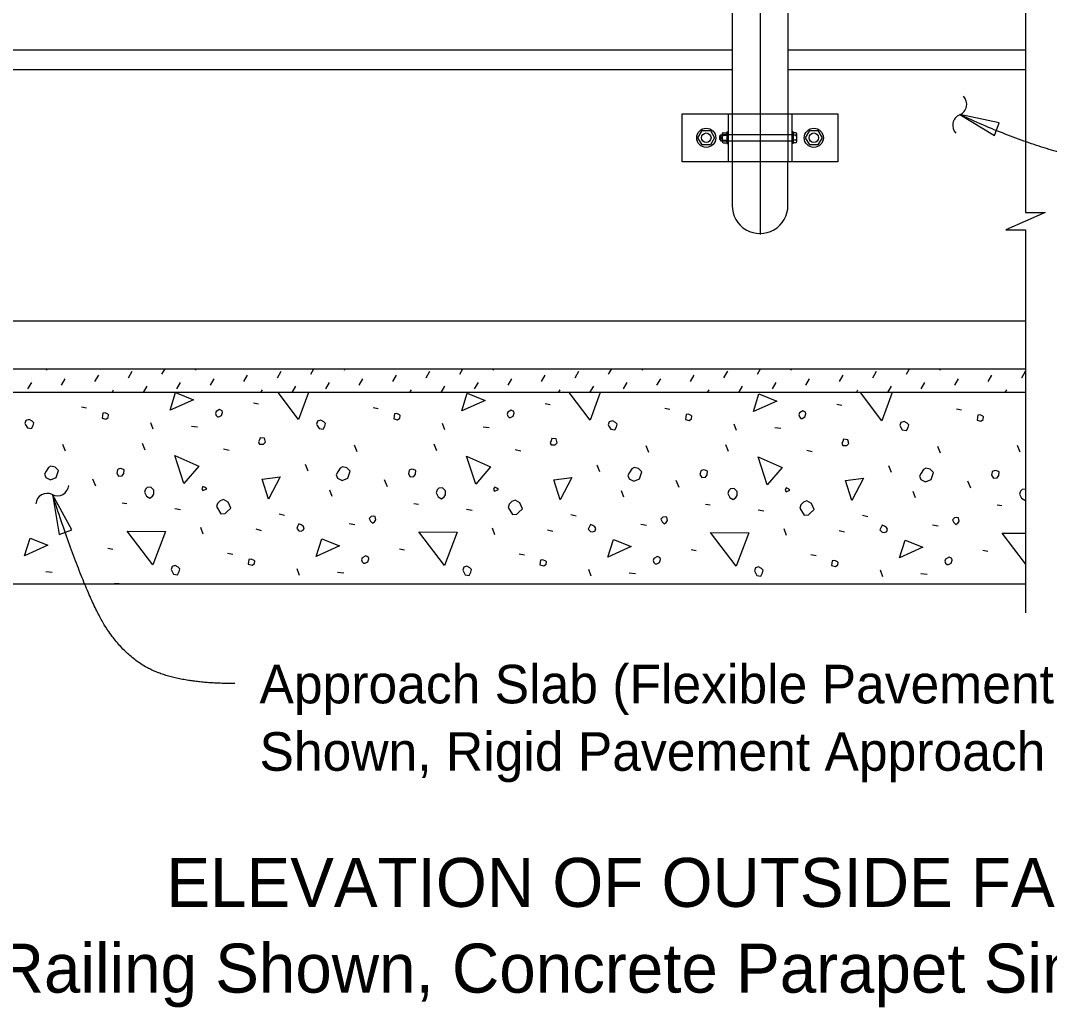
# Model space of a CAD drawing. Extents: x 0 to 41, y -96 to 25.
# Drawn here: x 10.75 to 16.13, y -84.87 to -79.71 of the extents above; entities that cross this region are included whole.
import ezdxf

# ---------------------------------------------------------------- set-up
doc = ezdxf.new("R2010")
doc.units = 0
for name, color, linetype in [('CL_Major', 7, 'Continuous'), ('Dimension', 7, 'Continuous'), ('Miscellaneous', 7, 'Continuous'), ('SteelMisc', 7, 'Continuous'), ('SteelMisc_h', 7, 'Continuous'), ('SupstrConc', 7, 'Continuous'), ('SupstrConc_h', 7, 'Continuous')]:
    doc.layers.add(name, color=color, linetype=linetype)

msp = doc.modelspace()

# ---------------------------------------------------------------- linework, layer by layer
at = {"layer": 'CL_Major'}
msp.add_line((14.615, -71.0824), (14.615, -80.8292), dxfattribs=at)
at = {"layer": 'Dimension'}
msp.add_lwpolyline([(16.002, -78.863), (16.002, -80.7139), (16.1053, -80.7139), (16.002, -80.7589), (15.8987, -80.8039), (16.002, -80.8039), (16.002, -82.8047)], dxfattribs=at)
for points in [[(15.6583, -80.2024), (15.8392, -80.3114), (15.865, -80.2458)], [(10.9179, -82.187), (10.9525, -82.3954), (11.0192, -82.3724)]]:
    msp.add_lwpolyline(points, close=True, dxfattribs=at)
for centre, start, end in [((15.6351, -80.1482), 292.7091, 44.4364), ((15.6811, -80.2581), 112.7091, 224.4364), ((10.8904, -82.2406), 63.2317, 174.9589), ((10.944, -82.1341), 243.2317, 354.9589)]:
    msp.add_arc(centre, 0.0596, start, end, dxfattribs=at)
for points in [[(16.9853, -80.4594), (16.9154, -80.4594), (16.2159, -80.4594), (15.6583, -80.2024)], [(11.8715, -83.1748), (11.6062, -83.1748), (11.3076, -83.0503), (11.092, -82.7183), (10.9179, -82.1871)]]:
    msp.add_open_spline(points, degree=2, dxfattribs=at)
at = {"layer": 'Miscellaneous'}
for p, q in [((14.4075, -80.3301), (14.4075, -80.318)), ((14.4132, -80.3301), (14.4132, -80.318)), ((10.8876, -81.5381), (10.8924, -81.5298)), ((11.4904, -81.5575), (11.5065, -81.5298)), ((11.6655, -81.5381), (11.6703, -81.5298)), ((12.2683, -81.5575), (12.2843, -81.5298)), ((12.4433, -81.5381), (12.4481, -81.5298)), ((13.0461, -81.5575), (13.0621, -81.5298)), ((13.2211, -81.5381), (13.2259, -81.5298)), ((13.8239, -81.5575), (13.84, -81.5298)), ((13.9989, -81.5381), (14.0037, -81.5298)), ((14.6017, -81.5575), (14.6178, -81.5298)), ((14.7767, -81.5381), (14.7815, -81.5298)), ((15.3795, -81.5575), (15.3956, -81.5298)), ((15.5545, -81.5381), (15.5593, -81.5298)), ((10.9654, -81.6158), (10.9849, -81.5823)), ((11.1404, -81.5964), (11.1599, -81.5628)), ((11.3154, -81.577), (11.3349, -81.5434)), ((11.7432, -81.6158), (11.7627, -81.5823)), ((11.9182, -81.5964), (11.9377, -81.5628)), ((12.0933, -81.577), (12.1127, -81.5434)), ((12.5211, -81.6158), (12.5405, -81.5823)), ((12.6961, -81.5964), (12.7155, -81.5628)), ((12.8711, -81.577), (12.8905, -81.5434)), ((13.2989, -81.6158), (13.3183, -81.5823)), ((13.4739, -81.5964), (13.4933, -81.5628)), ((13.6489, -81.577), (13.6683, -81.5434)), ((14.0767, -81.6158), (14.0961, -81.5823)), ((14.2517, -81.5964), (14.2711, -81.5628)), ((14.4267, -81.577), (14.4462, -81.5434)), ((14.8545, -81.6158), (14.874, -81.5823)), ((15.0295, -81.5964), (15.049, -81.5628)), ((15.2045, -81.577), (15.224, -81.5434)), ((15.6323, -81.6158), (15.6518, -81.5823)), ((15.8073, -81.5964), (15.8268, -81.5628)), ((15.9823, -81.577), (16.0018, -81.5434)), ((10.7904, -81.6353), (10.8099, -81.6017)), ((11.2295, -81.6547), (11.2377, -81.6406)), ((11.3932, -81.6547), (11.4127, -81.6211)), ((11.5682, -81.6353), (11.5877, -81.6017)), ((12.0073, -81.6547), (12.0155, -81.6406)), ((12.171, -81.6547), (12.1905, -81.6211)), ((12.346, -81.6353), (12.3655, -81.6017)), ((12.7851, -81.6547), (12.7933, -81.6406)), ((12.9489, -81.6547), (12.9683, -81.6211)), ((13.1239, -81.6353), (13.1433, -81.6017)), ((13.5629, -81.6547), (13.5711, -81.6406)), ((13.7267, -81.6547), (13.7461, -81.6211)), ((13.9017, -81.6353), (13.9211, -81.6017)), ((14.3407, -81.6547), (14.3489, -81.6406)), ((14.5045, -81.6547), (14.5239, -81.6211)), ((14.6795, -81.6353), (14.6989, -81.6017)), ((15.1186, -81.6547), (15.1267, -81.6406)), ((15.2823, -81.6547), (15.3018, -81.6211)), ((15.4573, -81.6353), (15.4768, -81.6017)), ((15.8964, -81.6547), (15.9046, -81.6406)), ((11.0699, -81.729), (11.0964, -81.7343)), ((11.9679, -81.7078), (11.9945, -81.7131)), ((12.5937, -81.7325), (12.6202, -81.7378)), ((13.4917, -81.7113), (13.5183, -81.7166)), ((14.1175, -81.736), (14.1441, -81.7414)), ((15.0156, -81.7148), (15.0421, -81.7201)), ((15.6414, -81.7396), (15.6679, -81.7449)), ((11.4447, -81.8457), (11.4323, -81.8121)), ((11.6444, -81.8297), (11.6763, -81.8333)), ((12.9685, -81.8492), (12.9561, -81.8156)), ((13.1682, -81.8333), (13.2001, -81.8368)), ((14.4923, -81.8527), (14.4799, -81.8191)), ((14.6921, -81.8368), (14.7239, -81.8403)), ((10.9868, -81.9606), (10.9727, -81.9252)), ((11.4022, -81.9553), (11.3881, -81.9199)), ((11.8124, -81.9482), (11.8407, -81.9553)), ((12.5106, -81.9641), (12.4965, -81.9287)), ((12.9261, -81.9588), (12.9119, -81.9234)), ((13.3362, -81.9517), (13.3645, -81.9588)), ((14.0345, -81.9676), (14.0203, -81.9323)), ((14.4499, -81.9623), (14.4357, -81.927)), ((14.86, -81.9553), (14.8883, -81.9623)), ((15.5583, -81.9712), (15.5441, -81.9358)), ((15.9737, -81.9659), (15.9596, -81.9305)), ((12.2543, -82.0649), (12.2402, -82.0295)), ((13.7781, -82.0684), (13.764, -82.033)), ((15.3019, -82.0719), (15.2878, -82.0366)), ((11.1442, -82.1426), (11.13, -82.1073)), ((12.668, -82.1462), (12.6538, -82.1108)), ((14.1918, -82.1497), (14.1776, -82.1144)), ((15.7156, -82.1532), (15.7015, -82.1179)), ((12.3798, -82.1974), (12.3675, -82.1638)), ((13.9036, -82.201), (13.8913, -82.1674)), ((15.4275, -82.2045), (15.4151, -82.1709)), ((11.282, -82.231), (11.3068, -82.2346)), ((12.8059, -82.2346), (12.8306, -82.2381)), ((14.3297, -82.2381), (14.3544, -82.2416)), ((15.8535, -82.2416), (15.8782, -82.2452)), ((11.5578, -82.2593), (11.5879, -82.2646)), ((12.1023, -82.2876), (12.1306, -82.2947)), ((13.0816, -82.2628), (13.1117, -82.2681)), ((13.6261, -82.2911), (13.6544, -82.2982)), ((14.6054, -82.2664), (14.6355, -82.2717)), ((15.1499, -82.2947), (15.1782, -82.3017)), ((12.4682, -82.3389), (12.4983, -82.3442)), ((13.992, -82.3424), (14.0221, -82.3477)), ((15.5158, -82.3459), (15.5459, -82.3512)), ((11.7063, -82.3937), (11.6939, -82.3601)), ((11.9803, -82.3671), (12.0086, -82.3742)), ((13.2301, -82.3972), (13.2177, -82.3636)), ((13.5041, -82.3707), (13.5324, -82.3777)), ((14.7539, -82.4007), (14.7416, -82.3671)), ((15.0279, -82.3742), (15.0562, -82.3813)), ((11.2078, -82.4679), (11.2343, -82.4732)), ((11.8336, -82.4927), (11.8601, -82.498)), ((12.7316, -82.4714), (12.7581, -82.4767)), ((13.3574, -82.4962), (13.3839, -82.5015)), ((14.2554, -82.475), (14.2819, -82.4803)), ((14.8812, -82.4997), (14.9077, -82.505)), ((15.7792, -82.4785), (15.8058, -82.4838)), ((10.8843, -82.5899), (10.9161, -82.5934)), ((12.2084, -82.6093), (12.196, -82.5757)), ((12.4081, -82.5934), (12.4399, -82.597)), ((13.7322, -82.6129), (13.7198, -82.5793)), ((13.9319, -82.597), (13.9637, -82.6005)), ((15.256, -82.6164), (15.2436, -82.5828)), ((15.4557, -82.6005), (15.4876, -82.604))]:
    msp.add_line(p, q, dxfattribs=at)
for points in [[(11.5331, -81.7467), (11.5613, -81.6547), (11.655, -81.6919), (11.5331, -81.7467)], [(12.203, -81.7944), (12.0969, -81.6547)], [(12.2552, -81.6547), (12.203, -81.7944)], [(13.0569, -81.7502), (13.0852, -81.6583), (13.1789, -81.6954), (13.0569, -81.7502)], [(13.7269, -81.7979), (13.618, -81.6547)], [(13.7804, -81.6547), (13.7269, -81.7979)], [(14.5807, -81.7537), (14.609, -81.6618), (14.7027, -81.6989), (14.5807, -81.7537)], [(15.2507, -81.8015), (15.1392, -81.6547)], [(15.3055, -81.6547), (15.2507, -81.8015)], [(11.7806, -81.782), (11.7876, -81.782), (11.8018, -81.7749), (11.8071, -81.759), (11.8053, -81.7502), (11.7912, -81.7431), (11.7735, -81.7537), (11.7699, -81.7643), (11.7735, -81.7749), (11.7806, -81.782)], [(13.3044, -81.7855), (13.3114, -81.7855), (13.3256, -81.7785), (13.3309, -81.7626), (13.3291, -81.7537), (13.315, -81.7467), (13.2973, -81.7573), (13.2938, -81.7679), (13.2973, -81.7785), (13.3044, -81.7855)], [(14.8282, -81.7891), (14.8353, -81.7891), (14.8494, -81.782), (14.8547, -81.7661), (14.8529, -81.7573), (14.8388, -81.7502), (14.8211, -81.7608), (14.8176, -81.7714), (14.8211, -81.782), (14.8282, -81.7891)], [(10.7782, -81.8227), (10.7871, -81.8386), (10.8083, -81.8421), (10.8171, -81.8262), (10.8207, -81.8121), (10.8118, -81.8032), (10.7959, -81.7944), (10.78, -81.7997), (10.7747, -81.8156), (10.7782, -81.8227)], [(11.1777, -81.7873), (11.1972, -81.7926), (11.2096, -81.7838), (11.2113, -81.7714), (11.2078, -81.7679), (11.1937, -81.7608), (11.1813, -81.7626), (11.1795, -81.7749), (11.1777, -81.7873)], [(12.302, -81.8262), (12.3109, -81.8421), (12.3321, -81.8457), (12.3409, -81.8297), (12.3445, -81.8156), (12.3356, -81.8068), (12.3197, -81.7979), (12.3038, -81.8032), (12.2985, -81.8191), (12.302, -81.8262)], [(12.7016, -81.7909), (12.721, -81.7962), (12.7334, -81.7873), (12.7351, -81.7749), (12.7316, -81.7714), (12.7175, -81.7643), (12.7051, -81.7661), (12.7033, -81.7785), (12.7016, -81.7909)], [(13.8259, -81.8297), (13.8347, -81.8457), (13.8559, -81.8492), (13.8647, -81.8333), (13.8683, -81.8191), (13.8594, -81.8103), (13.8435, -81.8015), (13.8276, -81.8068), (13.8223, -81.8227), (13.8259, -81.8297)], [(14.2254, -81.7944), (14.2448, -81.7997), (14.2572, -81.7909), (14.259, -81.7785), (14.2554, -81.7749), (14.2413, -81.7679), (14.2289, -81.7696), (14.2271, -81.782), (14.2254, -81.7944)], [(15.3497, -81.8333), (15.3585, -81.8492), (15.3797, -81.8527), (15.3886, -81.8368), (15.3921, -81.8227), (15.3833, -81.8138), (15.3674, -81.805), (15.3514, -81.8103), (15.3461, -81.8262), (15.3497, -81.8333)], [(15.7492, -81.7979), (15.7686, -81.8032), (15.781, -81.7944), (15.7828, -81.782), (15.7792, -81.7785), (15.7651, -81.7714), (15.7527, -81.7732), (15.751, -81.7855), (15.7492, -81.7979)], [(11.9998, -81.9234), (12.021, -81.9234), (12.0316, -81.9128), (12.0263, -81.8934), (12.0033, -81.8916), (11.9998, -81.9022), (11.9945, -81.9111), (11.9998, -81.9234), (11.9962, -81.9199)], [(13.5236, -81.927), (13.5448, -81.927), (13.5554, -81.9164), (13.5501, -81.8969), (13.5271, -81.8951), (13.5236, -81.9058), (13.5183, -81.9146), (13.5236, -81.927), (13.52, -81.9234)], [(15.0474, -81.9305), (15.0686, -81.9305), (15.0792, -81.9199), (15.0739, -81.9005), (15.0509, -81.8987), (15.0474, -81.9093), (15.0421, -81.9181), (15.0474, -81.9305), (15.0438, -81.927)], [(11.6055, -82.1303), (11.5578, -81.9835), (11.6833, -82.0383), (11.6055, -82.1303)], [(13.1294, -82.1338), (13.0816, -81.9871), (13.2071, -82.0419), (13.1294, -82.1338)], [(14.6532, -82.1373), (14.6054, -81.9906), (14.731, -82.0454), (14.6532, -82.1373)], [(10.8843, -82.0984), (10.9073, -82.1108), (10.9373, -82.0984), (10.9497, -82.0613), (10.932, -82.0436), (10.909, -82.0383), (10.8984, -82.0454), (10.8861, -82.0649), (10.8772, -82.0808), (10.8843, -82.0984)], [(11.2538, -82.0755), (11.2626, -82.0914), (11.282, -82.0896), (11.2909, -82.0772), (11.2926, -82.0578), (11.2803, -82.0525), (11.2714, -82.0507), (11.2608, -82.0542), (11.2573, -82.0578), (11.2538, -82.0755)], [(12.4081, -82.102), (12.4311, -82.1144), (12.4611, -82.102), (12.4735, -82.0649), (12.4558, -82.0472), (12.4329, -82.0419), (12.4223, -82.0489), (12.4099, -82.0684), (12.401, -82.0843), (12.4081, -82.102)], [(12.7776, -82.079), (12.7864, -82.0949), (12.8059, -82.0931), (12.8147, -82.0808), (12.8165, -82.0613), (12.8041, -82.056), (12.7952, -82.0542), (12.7846, -82.0578), (12.7811, -82.0613), (12.7776, -82.079)], [(13.9319, -82.1055), (13.9549, -82.1179), (13.985, -82.1055), (13.9973, -82.0684), (13.9797, -82.0507), (13.9567, -82.0454), (13.9461, -82.0525), (13.9337, -82.0719), (13.9249, -82.0878), (13.9319, -82.1055)], [(14.3014, -82.0825), (14.3102, -82.0984), (14.3297, -82.0967), (14.3385, -82.0843), (14.3403, -82.0649), (14.3279, -82.0596), (14.3191, -82.0578), (14.3085, -82.0613), (14.3049, -82.0649), (14.3014, -82.0825)], [(15.4557, -82.109), (15.4787, -82.1214), (15.5088, -82.109), (15.5211, -82.0719), (15.5035, -82.0542), (15.4805, -82.0489), (15.4699, -82.056), (15.4575, -82.0755), (15.4487, -82.0914), (15.4557, -82.109)], [(15.8252, -82.0861), (15.834, -82.102), (15.8535, -82.1002), (15.8623, -82.0878), (15.8641, -82.0684), (15.8517, -82.0631), (15.8429, -82.0613), (15.8323, -82.0649), (15.8287, -82.0684), (15.8252, -82.0861)], [(12.0475, -82.2116), (12.0139, -82.1073), (12.1076, -82.0949), (12.0475, -82.2116)], [(13.5713, -82.2151), (13.5377, -82.1108), (13.6314, -82.0984), (13.5713, -82.2151)], [(15.0951, -82.2187), (15.0615, -82.1144), (15.1552, -82.102), (15.0951, -82.2187)], [(11.3987, -82.1745), (11.4093, -82.1957), (11.427, -82.2063), (11.4411, -82.1957), (11.4482, -82.1851), (11.4482, -82.1638), (11.4323, -82.1479), (11.4129, -82.1497), (11.404, -82.1585), (11.3987, -82.1745)], [(11.7045, -82.1656), (11.724, -82.1568), (11.7169, -82.1497), (11.7045, -82.1444), (11.6992, -82.1568), (11.7045, -82.1656)], [(12.9225, -82.178), (12.9331, -82.1992), (12.9508, -82.2098), (12.965, -82.1992), (12.972, -82.1886), (12.972, -82.1674), (12.9561, -82.1515), (12.9367, -82.1532), (12.9278, -82.1621), (12.9225, -82.178)], [(13.2284, -82.1692), (13.2478, -82.1603), (13.2407, -82.1532), (13.2284, -82.1479), (13.223, -82.1603), (13.2284, -82.1692)], [(14.4463, -82.1815), (14.457, -82.2027), (14.4746, -82.2133), (14.4888, -82.2027), (14.4958, -82.1921), (14.4958, -82.1709), (14.4799, -82.155), (14.4605, -82.1568), (14.4516, -82.1656), (14.4463, -82.1815)], [(14.7522, -82.1727), (14.7716, -82.1638), (14.7645, -82.1568), (14.7522, -82.1515), (14.7469, -82.1638), (14.7522, -82.1727)], [(16.002, -82.1587), (15.9843, -82.1603), (15.9755, -82.1692), (15.9702, -82.1851)], [(15.9702, -82.1851), (15.9808, -82.2063), (15.9984, -82.2169), (16.002, -82.2142)], [(11.7752, -82.2505), (11.7982, -82.2876), (11.8212, -82.2858), (11.83, -82.277), (11.8495, -82.2575), (11.8371, -82.2275), (11.8124, -82.2133), (11.7947, -82.2204), (11.7806, -82.2346), (11.7752, -82.2505)], [(13.2991, -82.254), (13.322, -82.2911), (13.345, -82.2894), (13.3539, -82.2805), (13.3733, -82.2611), (13.3609, -82.231), (13.3362, -82.2169), (13.3185, -82.224), (13.3044, -82.2381), (13.2991, -82.254)], [(14.8229, -82.2575), (14.8459, -82.2947), (14.8688, -82.2929), (14.8777, -82.2841), (14.8971, -82.2646), (14.8848, -82.2346), (14.86, -82.2204), (14.8423, -82.2275), (14.8282, -82.2416), (14.8229, -82.2575)], [(12.2048, -82.376), (12.2172, -82.3777), (12.2296, -82.3724), (12.2331, -82.3618), (12.2278, -82.353), (12.2172, -82.3459), (12.2048, -82.3406), (12.1977, -82.3548), (12.1942, -82.3654), (12.2048, -82.376)], [(12.5796, -82.3265), (12.5902, -82.3371), (12.6008, -82.33), (12.6079, -82.3194), (12.6043, -82.3017), (12.5955, -82.3), (12.5831, -82.3017), (12.5725, -82.3123), (12.5796, -82.3265)], [(13.7286, -82.3795), (13.741, -82.3813), (13.7534, -82.376), (13.7569, -82.3654), (13.7516, -82.3565), (13.741, -82.3495), (13.7286, -82.3442), (13.7216, -82.3583), (13.718, -82.3689), (13.7286, -82.3795)], [(14.1034, -82.33), (14.114, -82.3406), (14.1246, -82.3336), (14.1317, -82.3229), (14.1281, -82.3053), (14.1193, -82.3035), (14.1069, -82.3053), (14.0963, -82.3159), (14.1034, -82.33)], [(15.2524, -82.3831), (15.2648, -82.3848), (15.2772, -82.3795), (15.2807, -82.3689), (15.2754, -82.3601), (15.2648, -82.353), (15.2524, -82.3477), (15.2454, -82.3618), (15.2418, -82.3724), (15.2524, -82.3831)], [(15.6272, -82.3336), (15.6378, -82.3442), (15.6484, -82.3371), (15.6555, -82.3265), (15.652, -82.3088), (15.6431, -82.307), (15.6307, -82.3088), (15.6201, -82.3194), (15.6272, -82.3336)], [(11.4429, -82.5545), (11.3086, -82.3777), (11.5083, -82.3795), (11.4429, -82.5545)], [(12.9667, -82.5581), (12.8324, -82.3813), (13.0321, -82.3831), (12.9667, -82.5581)], [(14.4905, -82.5616), (14.3562, -82.3848), (14.5559, -82.3866), (14.4905, -82.5616)], [(16.002, -82.5489), (15.88, -82.3884), (16.002, -82.3894)], [(10.7729, -82.5068), (10.8012, -82.4149), (10.8949, -82.452), (10.7729, -82.5068)], [(12.2967, -82.5103), (12.325, -82.4184), (12.4187, -82.4555), (12.2967, -82.5103)], [(13.8206, -82.5139), (13.8488, -82.4219), (13.9425, -82.4591), (13.8206, -82.5139)], [(15.3444, -82.5174), (15.3727, -82.4255), (15.4663, -82.4626), (15.3444, -82.5174)], [(12.5442, -82.5457), (12.5513, -82.5457), (12.5654, -82.5386), (12.5707, -82.5227), (12.569, -82.5139), (12.5548, -82.5068), (12.5372, -82.5174), (12.5336, -82.528), (12.5372, -82.5386), (12.5442, -82.5457)], [(14.068, -82.5492), (14.0751, -82.5492), (14.0893, -82.5422), (14.0946, -82.5262), (14.0928, -82.5174), (14.0786, -82.5103), (14.061, -82.5209), (14.0574, -82.5315), (14.061, -82.5422), (14.068, -82.5492)], [(11.5419, -82.5863), (11.5507, -82.6023), (11.572, -82.6058), (11.5808, -82.5899), (11.5843, -82.5757), (11.5755, -82.5669), (11.5596, -82.5581), (11.5437, -82.5634), (11.5384, -82.5793), (11.5419, -82.5863)], [(11.9414, -82.551), (11.9609, -82.5563), (11.9732, -82.5475), (11.975, -82.5351), (11.9715, -82.5315), (11.9573, -82.5245), (11.945, -82.5262), (11.9432, -82.5386), (11.9414, -82.551)], [(13.0657, -82.5899), (13.0746, -82.6058), (13.0958, -82.6093), (13.1046, -82.5934), (13.1081, -82.5793), (13.0993, -82.5704), (13.0834, -82.5616), (13.0675, -82.5669), (13.0622, -82.5828), (13.0657, -82.5899)], [(13.4652, -82.5545), (13.4847, -82.5598), (13.4971, -82.551), (13.4988, -82.5386), (13.4953, -82.5351), (13.4811, -82.528), (13.4688, -82.5298), (13.467, -82.5422), (13.4652, -82.5545)], [(14.989, -82.5581), (15.0085, -82.5634), (15.0209, -82.5545), (15.0226, -82.5422), (15.0191, -82.5386), (15.005, -82.5315), (14.9926, -82.5333), (14.9908, -82.5457), (14.989, -82.5581)], [(15.5919, -82.5528), (15.5989, -82.5528), (15.6131, -82.5457), (15.6184, -82.5298), (15.6166, -82.5209), (15.6025, -82.5139), (15.5848, -82.5245), (15.5813, -82.5351), (15.5848, -82.5457), (15.5919, -82.5528)], [(14.5895, -82.5934), (14.5984, -82.6093), (14.6196, -82.6129), (14.6284, -82.597), (14.632, -82.5828), (14.6231, -82.574), (14.6072, -82.5651), (14.5913, -82.5704), (14.586, -82.5863), (14.5895, -82.5934)], [(11.2665, -82.6547), (11.2661, -82.6535), (11.2432, -82.6518), (11.2422, -82.6547)]]:
    msp.add_lwpolyline(points, dxfattribs=at)
at = {"layer": 'SteelMisc'}
for p, q in [((14.4692, -79.4482), (14.4692, -80.1982)), ((14.7609, -79.4482), (14.7609, -80.1982)), ((14.2091, -80.1982), (15.021, -80.1982)), ((14.2091, -80.4482), (14.2091, -80.1982)), ((14.4484, -80.1982), (14.4484, -80.4482)), ((14.7817, -80.1982), (14.7817, -80.4482)), ((15.021, -80.1982), (15.021, -80.4482)), ((14.4168, -80.3053), (14.4168, -80.341)), ((14.4217, -80.2972), (14.4418, -80.2972)), ((14.4418, -80.2929), (14.4418, -80.3535)), ((14.4418, -80.2929), (14.4484, -80.2929)), ((14.4418, -80.2972), (14.4418, -80.3492)), ((14.788, -80.2929), (14.782, -80.2929)), ((14.788, -80.2929), (14.788, -80.3535)), ((14.8027, -80.2972), (14.788, -80.2972)), ((14.8078, -80.3426), (14.8078, -80.3037)), ((14.4047, -80.3152), (14.4103, -80.3086)), ((14.4047, -80.3329), (14.4047, -80.3152)), ((14.4047, -80.3329), (14.4103, -80.3385)), ((14.4103, -80.3086), (14.4168, -80.3086)), ((14.4103, -80.3385), (14.4103, -80.3086)), ((14.4103, -80.3385), (14.4168, -80.3385)), ((14.4215, -80.3102), (14.4418, -80.3102)), ((14.4215, -80.3361), (14.4418, -80.3361)), ((14.4218, -80.3492), (14.4418, -80.3492)), ((14.4418, -80.3535), (14.4484, -80.3535)), ((14.788, -80.3535), (14.782, -80.3535)), ((14.8028, -80.3102), (14.788, -80.3102)), ((14.8028, -80.3362), (14.788, -80.3362)), ((14.8027, -80.3492), (14.788, -80.3492)), ((15.021, -80.4482), (14.2091, -80.4482)), ((14.4691, -80.4482), (14.4691, -80.6774)), ((14.7608, -80.6774), (14.7608, -80.4482))]:
    msp.add_line(p, q, dxfattribs=at)
for points in [[(14.3124, -80.2857), (14.3557, -80.2857), (14.3774, -80.3232), (14.3557, -80.3607), (14.3124, -80.3607), (14.2907, -80.3232)], [(14.8744, -80.2857), (14.9177, -80.2857), (14.9394, -80.3232), (14.9177, -80.3607), (14.8744, -80.3607), (14.8527, -80.3232)]]:
    msp.add_lwpolyline(points, close=True, dxfattribs=at)
for centre, radius in [((14.3341, -80.3232), 0.05), ((14.3341, -80.3232), 0.025), ((14.896, -80.3232), 0.05), ((14.896, -80.3232), 0.025)]:
    msp.add_circle(centre, radius, dxfattribs=at)
for centre, radius, start, end in [((14.4234, -80.3038), 0.00674, 104.4891, 254.1889), ((14.801, -80.3038), 0.00673, 285.7823, 75.5404), ((14.4363, -80.3232), 0.0196, 138.628, 221.372), ((14.4234, -80.3427), 0.00673, 105.7823, 255.5404), ((14.801, -80.3427), 0.00674, 284.4891, 74.1889), ((14.7881, -80.3232), 0.0196, 318.628, 41.372)]:
    msp.add_arc(centre, radius, start, end, dxfattribs=at)
msp.add_ellipse((14.615, -80.6774), major_axis=(0, 0.1458), ratio=0.999499, start_param=1.570796, end_param=4.712389, dxfattribs=at)
at = {"layer": 'SteelMisc_h'}
for p, q in [((14.4692, -80.1982), (14.4692, -80.4482)), ((14.7609, -80.1982), (14.7609, -80.4482)), ((14.7817, -80.3086), (14.4168, -80.3086)), ((14.4168, -80.3385), (14.7817, -80.3385))]:
    msp.add_line(p, q, dxfattribs=at)
at = {"layer": 'SupstrConc'}
for p, q in [((4.7609, -79.8631), (14.4692, -79.8631)), ((14.7609, -79.8631), (16.002, -79.8631)), ((4.7609, -79.9673), (14.4692, -79.9673)), ((14.7609, -79.9673), (16.002, -79.9673)), ((3.615, -81.5298), (16.002, -81.5298)), ((16.002, -81.6547), (3.615, -81.6547)), ((16.002, -82.6547), (3.615, -82.6547))]:
    msp.add_line(p, q, dxfattribs=at)
at = {"layer": 'SupstrConc_h'}
msp.add_line((3.615, -81.2797), (16.002, -81.2797), dxfattribs=at)

# ---------------------------------------------------------------- texts
at = {"layer": 'Dimension'}
for s, height, p in [('Approach Slab (Flexible Pavement Approach Slab ', 0.2016, (11.9999, -83.2783)), ('Shown, Rigid Pavement Approach Slab Similar)', 0.2016, (11.9999, -83.6303)), ('ELEVATION OF OUTSIDE FACE OF RAILING', 0.256001, (11.5134, -84.3415)), ('(Traffic Railing Shown, Concrete Parapet Similar (See Note 3))', 0.256001, (9.4668, -84.7895))]:
    msp.add_text(s, height=height, dxfattribs=at).set_placement(p)

doc.saveas('drawing.dxf')
